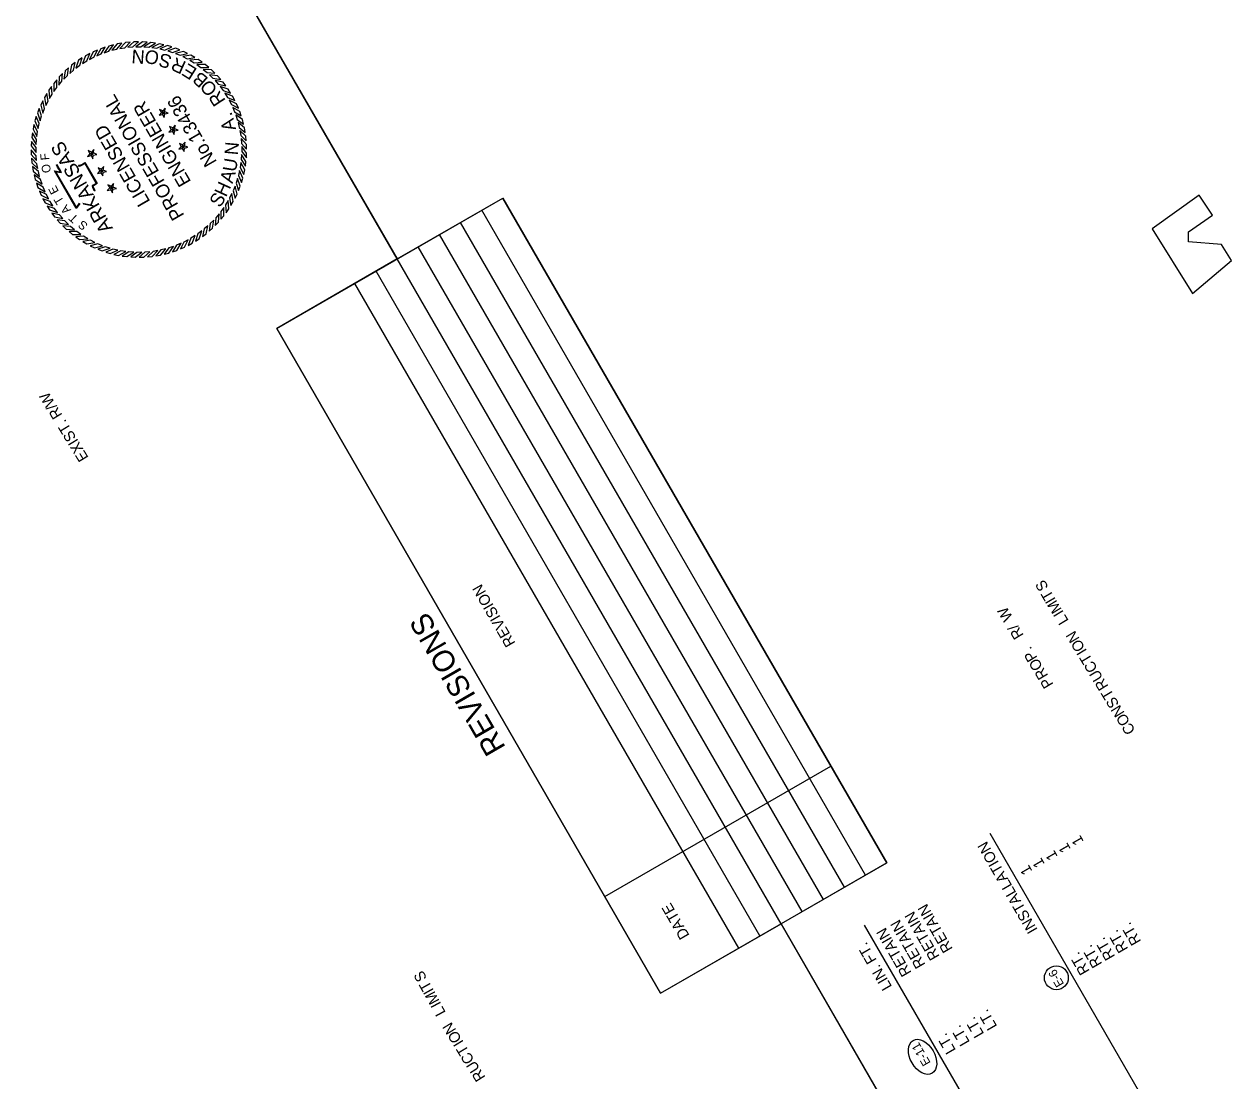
# Model space of a CAD drawing. Extents: x 956270 to 957915, y 1920230 to 1922423.
# Drawn here: x 956610 to 957279, y 1921447 to 1922032 of the extents above; entities that cross this region are included whole.
import ezdxf

# ---------------------------------------------------------------- set-up
doc = ezdxf.new("R2010")
doc.units = 0
for name, color, linetype in [('1', 7, 'Continuous'), ('44', 7, 'Continuous'), ('Default', 7, 'Continuous'), ('G-ANNO-SYMB', 7, 'Continuous'), ('NO PLOT', 7, 'Continuous'), ('R_Draft', 7, 'Continuous')]:
    doc.layers.add(name, color=color, linetype=linetype)

msp = doc.modelspace()

# ---------------------------------------------------------------- linework, layer by layer
at = {"layer": '1'}
for p, q in [((956816.66, 1921901.98), (956666.17, 1922162.65)), ((957172.25, 1921286.08), (957029.16, 1921533.92))]:
    msp.add_line(p, q, dxfattribs=at)
msp.add_circle((957181.5, 1921504.03), 6.61, dxfattribs=at)
msp.add_ellipse((957107.43, 1921460.25), major_axis=(-5.26, 9.11), ratio=0.638788, dxfattribs=at)
at = {"layer": '44'}
for p, q in [((957265.37, 1921375.21), (957144.87, 1921583.93)), ((957191.79, 1921331.56), (957075.39, 1921533.17))]:
    msp.add_line(p, q, dxfattribs=at)
at = {"layer": 'Default'}
for p, q in [((956749.98, 1921863.48), (956875.12, 1921935.73)), ((957087.62, 1921567.67), (956875.12, 1921935.73)), ((957075.93, 1921560.92), (956863.43, 1921928.98)), ((957064.24, 1921554.17), (956851.74, 1921922.23)), ((957052.55, 1921547.42), (956840.05, 1921915.48)), ((957040.85, 1921540.67), (956828.35, 1921908.73)), ((957040.85, 1921540.67), (956828.35, 1921908.73)), ((957029.16, 1921533.92), (956816.66, 1921901.98)), ((957017.47, 1921527.17), (956804.97, 1921895.23)), ((957005.78, 1921520.42), (956793.28, 1921888.48)), ((956962.48, 1921495.42), (956749.98, 1921863.48)), ((956931.57, 1921548.95), (957056.71, 1921621.2)), ((956962.48, 1921495.42), (957087.62, 1921567.67))]:
    msp.add_line(p, q, dxfattribs=at)
at = {"layer": 'G-ANNO-SYMB'}
for points in [[(956668.87, 1922022.03), (956666.32, 1922021.77), (956663.11, 1922018.51), (956665.85, 1922018.95)], [(956673.55, 1922022.22), (956670.99, 1922022.16), (956667.53, 1922019.16), (956670.3, 1922019.4)], [(956678.23, 1922022.05), (956675.67, 1922022.19), (956671.99, 1922019.47), (956674.77, 1922019.49)], [(956682.89, 1922021.51), (956680.34, 1922021.85), (956676.46, 1922019.43), (956679.23, 1922019.23)], [(956646.48, 1922015.66), (956644.22, 1922014.44), (956642.51, 1922010.2), (956644.87, 1922011.66)], [(956650.73, 1922017.63), (956648.38, 1922016.59), (956646.34, 1922012.5), (956648.81, 1922013.77)], [(956655.12, 1922019.26), (956652.7, 1922018.41), (956650.35, 1922014.49), (956652.9, 1922015.56)], [(956659.63, 1922020.54), (956657.15, 1922019.88), (956654.49, 1922016.16), (956657.12, 1922017.03)], [(956664.22, 1922021.47), (956661.7, 1922021.01), (956658.76, 1922017.5), (956661.45, 1922018.16)], [(956687.48, 1922020.61), (956684.97, 1922021.15), (956680.92, 1922019.04), (956683.66, 1922018.62)], [(956691.99, 1922019.35), (956689.54, 1922020.08), (956685.33, 1922018.3), (956688.02, 1922017.66)], [(956696.39, 1922017.74), (956694, 1922018.66), (956689.66, 1922017.21), (956692.3, 1922016.37)], [(956700.65, 1922015.79), (956698.34, 1922016.9), (956693.9, 1922015.79), (956696.47, 1922014.74)], [(956638.51, 1922010.75), (956636.47, 1922009.19), (956635.44, 1922004.73), (956637.54, 1922006.55)], [(956642.4, 1922013.36), (956640.24, 1922011.97), (956638.87, 1922007.6), (956641.1, 1922009.25)], [(956704.74, 1922013.51), (956702.52, 1922014.8), (956698.01, 1922014.04), (956700.49, 1922012.8)], [(956708.64, 1922010.91), (956706.53, 1922012.37), (956701.98, 1922011.97), (956704.35, 1922010.54)], [(956712.33, 1922008.02), (956710.34, 1922009.64), (956705.77, 1922009.6), (956708.02, 1922007.99)], [(956631.41, 1922004.65), (956629.64, 1922002.79), (956629.32, 1921998.23), (956631.11, 1922000.35)], [(956634.84, 1922007.84), (956632.93, 1922006.12), (956632.25, 1922001.6), (956634.2, 1922003.57)], [(956715.78, 1922004.85), (956713.92, 1922006.62), (956709.36, 1922006.94), (956711.48, 1922005.15)], [(956718.97, 1922001.42), (956717.25, 1922003.33), (956712.73, 1922004.01), (956714.7, 1922002.06)], [(956625.34, 1921997.52), (956623.89, 1921995.4), (956624.28, 1921990.85), (956625.72, 1921993.22)], [(956628.24, 1922001.2), (956626.62, 1921999.21), (956626.66, 1921994.64), (956628.27, 1921996.89)], [(956721.88, 1921997.75), (956720.32, 1921999.79), (956715.86, 1922000.82), (956717.67, 1921998.72)], [(956724.49, 1921993.86), (956723.09, 1921996.01), (956718.73, 1921997.39), (956720.37, 1921995.16)], [(956620.47, 1921989.52), (956619.36, 1921987.21), (956620.47, 1921982.77), (956621.52, 1921985.34)], [(956622.75, 1921993.61), (956621.46, 1921991.4), (956622.22, 1921986.89), (956623.46, 1921989.36)], [(956726.79, 1921989.78), (956725.57, 1921992.03), (956721.33, 1921993.75), (956722.79, 1921991.39)], [(956728.76, 1921985.53), (956727.72, 1921987.87), (956723.63, 1921989.91), (956724.9, 1921987.45)], [(956618.52, 1921985.26), (956617.6, 1921982.87), (956619.05, 1921978.53), (956619.89, 1921981.17)], [(956687.23, 1921982.98), (956686.19, 1921983.08), (956684.87, 1921981.61), (956686.8, 1921982.02)], [(956687.23, 1921982.98), (956687.01, 1921983.99), (956685.2, 1921984.8), (956686.19, 1921983.08)], [(956687.23, 1921982.98), (956686.8, 1921982.02), (956687.79, 1921980.31), (956688, 1921982.28)], [(956687.23, 1921982.98), (956688.13, 1921983.5), (956688.34, 1921985.47), (956687.01, 1921983.99)], [(956687.23, 1921982.98), (956688, 1921982.28), (956689.94, 1921982.69), (956688.13, 1921983.5)], [(956730.39, 1921981.14), (956729.54, 1921983.56), (956725.62, 1921985.91), (956726.69, 1921983.36)], [(956731.67, 1921976.63), (956731.01, 1921979.11), (956727.29, 1921981.77), (956728.16, 1921979.14)], [(956615.65, 1921976.35), (956615.11, 1921973.84), (956617.22, 1921969.79), (956617.64, 1921972.53)], [(956616.91, 1921980.86), (956616.18, 1921978.41), (956617.96, 1921974.2), (956618.59, 1921976.9)], [(956692.68, 1921973.53), (956692.47, 1921974.55), (956690.66, 1921975.35), (956691.65, 1921973.64)], [(956692.68, 1921973.53), (956693.58, 1921974.05), (956693.79, 1921976.02), (956692.47, 1921974.55)], [(956732.6, 1921972.04), (956732.13, 1921974.56), (956728.63, 1921977.5), (956729.29, 1921974.81)], [(956614.75, 1921971.76), (956614.41, 1921969.21), (956616.83, 1921965.34), (956617.03, 1921968.1)], [(956692.68, 1921973.53), (956691.65, 1921973.64), (956690.32, 1921972.16), (956692.26, 1921972.58)], [(956692.68, 1921973.53), (956692.26, 1921972.58), (956693.25, 1921970.86), (956693.46, 1921972.83)], [(956692.68, 1921973.53), (956693.46, 1921972.83), (956695.39, 1921973.24), (956693.58, 1921974.05)], [(956733.16, 1921967.39), (956732.9, 1921969.94), (956729.63, 1921973.15), (956730.08, 1921970.41)], [(956733.35, 1921962.71), (956733.29, 1921965.27), (956730.29, 1921968.72), (956730.52, 1921965.96)], [(956614.03, 1921962.42), (956614.1, 1921959.86), (956617.1, 1921956.41), (956616.86, 1921959.17)], [(956614.21, 1921967.1), (956614.07, 1921964.54), (956616.79, 1921960.87), (956616.77, 1921963.64)], [(956647.67, 1921960.13), (956647.45, 1921961.15), (956645.64, 1921961.96), (956646.63, 1921960.24)], [(956647.67, 1921960.13), (956648.57, 1921960.66), (956648.77, 1921962.63), (956647.45, 1921961.15)], [(956698.14, 1921964.08), (956697.1, 1921964.19), (956695.77, 1921962.72), (956697.71, 1921963.13)], [(956698.14, 1921964.08), (956697.92, 1921965.1), (956696.11, 1921965.91), (956697.1, 1921964.19)], [(956698.14, 1921964.08), (956697.71, 1921963.13), (956698.7, 1921961.41), (956698.91, 1921963.38)], [(956698.14, 1921964.08), (956699.04, 1921964.6), (956699.25, 1921966.57), (956697.92, 1921965.1)], [(956698.14, 1921964.08), (956698.91, 1921963.38), (956700.85, 1921963.8), (956699.04, 1921964.6)], [(956733.18, 1921958.03), (956733.32, 1921960.59), (956730.6, 1921964.26), (956730.62, 1921961.49)], [(956614.23, 1921957.74), (956614.49, 1921955.19), (956617.75, 1921951.98), (956617.31, 1921954.72)], [(956647.67, 1921960.13), (956646.63, 1921960.24), (956645.3, 1921958.77), (956647.24, 1921959.18)], [(956647.67, 1921960.13), (956647.24, 1921959.18), (956648.23, 1921957.47), (956648.44, 1921959.44)], [(956647.67, 1921960.13), (956648.44, 1921959.44), (956650.38, 1921959.85), (956648.57, 1921960.66)], [(956731.74, 1921948.78), (956732.28, 1921951.29), (956730.17, 1921955.34), (956729.75, 1921952.6)], [(956732.64, 1921953.37), (956732.98, 1921955.92), (956730.56, 1921959.79), (956730.36, 1921957.03)], [(956614.79, 1921953.09), (956615.25, 1921950.57), (956618.76, 1921947.63), (956618.09, 1921950.32)], [(956615.72, 1921948.5), (956616.37, 1921946.02), (956620.1, 1921943.36), (956619.23, 1921945.99)], [(956653.12, 1921950.69), (956652.08, 1921950.8), (956650.76, 1921949.32), (956652.7, 1921949.74)], [(956653.12, 1921950.69), (956652.9, 1921951.71), (956651.09, 1921952.51), (956652.08, 1921950.8)], [(956653.12, 1921950.69), (956652.7, 1921949.74), (956653.69, 1921948.02), (956653.89, 1921949.99)], [(956653.12, 1921950.69), (956654.02, 1921951.21), (956654.23, 1921953.18), (956652.9, 1921951.71)], [(956653.12, 1921950.69), (956653.89, 1921949.99), (956655.83, 1921950.4), (956654.02, 1921951.21)], [(956730.48, 1921944.27), (956731.21, 1921946.72), (956729.43, 1921950.93), (956728.79, 1921948.23)], [(956617, 1921943.99), (956617.85, 1921941.57), (956621.77, 1921939.22), (956620.69, 1921941.77)], [(956658.57, 1921941.24), (956658.36, 1921942.26), (956656.55, 1921943.06), (956657.54, 1921941.35)], [(956658.57, 1921941.24), (956659.48, 1921941.76), (956659.68, 1921943.73), (956658.36, 1921942.26)], [(956658.57, 1921941.24), (956659.35, 1921940.54), (956661.29, 1921940.95), (956659.48, 1921941.76)], [(956726.92, 1921935.61), (956728.03, 1921937.92), (956726.92, 1921942.36), (956725.87, 1921939.79)], [(956728.87, 1921939.87), (956729.79, 1921942.26), (956728.34, 1921946.6), (956727.5, 1921943.96)], [(956618.63, 1921939.6), (956619.67, 1921937.26), (956623.76, 1921935.22), (956622.49, 1921937.68)], [(956620.6, 1921935.35), (956621.82, 1921933.1), (956626.06, 1921931.38), (956624.6, 1921933.74)], [(956658.57, 1921941.24), (956657.54, 1921941.35), (956656.21, 1921939.88), (956658.15, 1921940.29)], [(956658.57, 1921941.24), (956658.15, 1921940.29), (956659.14, 1921938.57), (956659.35, 1921940.54)], [(956724.64, 1921931.52), (956725.92, 1921933.73), (956725.17, 1921938.24), (956723.93, 1921935.77)], [(956622.9, 1921931.27), (956624.29, 1921929.12), (956628.65, 1921927.74), (956627.01, 1921929.97)], [(956719.15, 1921923.93), (956720.77, 1921925.92), (956720.73, 1921930.49), (956719.11, 1921928.24)], [(956722.04, 1921927.61), (956723.5, 1921929.73), (956723.1, 1921934.28), (956721.67, 1921931.91)], [(956625.51, 1921927.38), (956627.07, 1921925.34), (956631.53, 1921924.31), (956629.71, 1921926.41)], [(956628.42, 1921923.71), (956630.13, 1921921.8), (956634.66, 1921921.12), (956632.69, 1921923.07)], [(956712.55, 1921917.29), (956714.46, 1921919.01), (956715.13, 1921923.53), (956713.19, 1921921.56)], [(956715.98, 1921920.48), (956717.75, 1921922.34), (956718.07, 1921926.9), (956716.28, 1921924.78)], [(956631.61, 1921920.28), (956633.47, 1921918.51), (956638.03, 1921918.19), (956635.91, 1921919.98)], [(956635.06, 1921917.11), (956637.05, 1921915.49), (956641.62, 1921915.53), (956639.37, 1921917.14)], [(956700.91, 1921909.47), (956703.16, 1921910.69), (956704.88, 1921914.93), (956702.52, 1921913.47)], [(956704.99, 1921911.77), (956707.14, 1921913.16), (956708.52, 1921917.53), (956706.28, 1921915.88)], [(956708.88, 1921914.38), (956710.92, 1921915.94), (956711.94, 1921920.4), (956709.85, 1921918.58)], [(956638.74, 1921914.22), (956640.85, 1921912.76), (956645.41, 1921913.16), (956643.04, 1921914.59)], [(956642.64, 1921911.62), (956644.86, 1921910.33), (956649.37, 1921911.09), (956646.9, 1921912.33)], [(956646.74, 1921909.34), (956649.05, 1921908.23), (956653.49, 1921909.34), (956650.92, 1921910.39)], [(956651, 1921907.39), (956653.39, 1921906.47), (956657.73, 1921907.92), (956655.08, 1921908.76)], [(956687.76, 1921904.59), (956690.24, 1921905.25), (956692.9, 1921908.97), (956690.26, 1921908.1)], [(956692.27, 1921905.87), (956694.69, 1921906.72), (956697.04, 1921910.64), (956694.49, 1921909.57)], [(956696.66, 1921907.5), (956699, 1921908.54), (956701.04, 1921912.63), (956698.58, 1921911.36)], [(956655.39, 1921905.78), (956657.85, 1921905.05), (956662.06, 1921906.83), (956659.36, 1921907.47)], [(956659.91, 1921904.52), (956662.41, 1921903.98), (956666.47, 1921906.09), (956663.73, 1921906.51)], [(956664.5, 1921903.62), (956667.05, 1921903.28), (956670.92, 1921905.7), (956668.16, 1921905.9)], [(956669.16, 1921903.08), (956671.72, 1921902.94), (956675.39, 1921905.66), (956672.62, 1921905.64)], [(956673.84, 1921902.91), (956676.4, 1921902.97), (956679.85, 1921905.97), (956677.09, 1921905.73)], [(956678.52, 1921903.1), (956681.07, 1921903.36), (956684.27, 1921906.62), (956681.54, 1921906.18)], [(956683.17, 1921903.66), (956685.69, 1921904.12), (956688.63, 1921907.63), (956685.94, 1921906.97)]]:
    msp.add_lwpolyline(points, close=True, dxfattribs=at)
for points in [[(956640.27, 1921954.03), (956640.76, 1921953.84), (956641.26, 1921953.97), (956642.41, 1921954.48), (956643.85, 1921955.31), (956650.57, 1921943.68), (956648.62, 1921942.56), (956648.19, 1921942.31), (956648.32, 1921941.75), (956649.27, 1921940.1), (956649, 1921939.54)], [(956640.97, 1921932.64), (956639.06, 1921929.93), (956627.02, 1921950.76), (956630.21, 1921950.28), (956629.37, 1921951.69), (956628.68, 1921952.86), (956628.12, 1921954.12)], [(956640.66, 1921932.86), (956639.09, 1921930.63), (956627.74, 1921950.27), (956630.95, 1921949.79), (956629.7, 1921951.88), (956629.02, 1921953.04), (956628.47, 1921954.27)], [(956640.13, 1921953.67), (956640.74, 1921953.44), (956641.39, 1921953.61), (956642.58, 1921954.14), (956643.71, 1921954.79), (956650.05, 1921943.82), (956648.43, 1921942.89), (956647.76, 1921942.5), (956647.96, 1921941.61), (956648.84, 1921940.08), (956648.65, 1921939.72)]]:
    msp.add_lwpolyline(points, dxfattribs=at)
at = {"layer": 'NO PLOT'}
for points in [[(957915.18, 1921041.6), (957117.5, 1922423.23), (956666.17, 1922162.65), (956816.66, 1921901.98), (956875.12, 1921935.73), (957087.62, 1921567.67), (957029.16, 1921533.92), (957172.25, 1921286.08), (957225.74, 1921316.96), (957397.07, 1921020.21), (957343.58, 1920989.33), (957463.85, 1920781.02)], [(957915.18, 1921041.6), (957117.5, 1922423.23), (956666.17, 1922162.65), (956816.66, 1921901.98), (956875.12, 1921935.73), (957087.62, 1921567.67), (957029.16, 1921533.92), (957172.25, 1921286.08), (957225.74, 1921316.96), (957397.07, 1921020.21), (957343.58, 1920989.33), (957463.85, 1920781.02)], [(957915.18, 1921041.6), (957117.5, 1922423.23), (956666.17, 1922162.65), (956816.66, 1921901.98), (956875.12, 1921935.73), (957087.62, 1921567.67), (957029.16, 1921533.92), (957172.25, 1921286.08), (957225.74, 1921316.96), (957397.07, 1921020.21), (957343.58, 1920989.33), (957463.85, 1920781.02)], [(957915.18, 1921041.6), (957117.5, 1922423.23), (956666.17, 1922162.65), (956816.66, 1921901.98), (956875.12, 1921935.73), (957087.62, 1921567.67), (957029.16, 1921533.92), (957172.25, 1921286.08), (957225.74, 1921316.96), (957397.07, 1921020.21), (957343.58, 1920989.33), (957463.85, 1920781.02)], [(957915.18, 1921041.6), (957117.5, 1922423.23), (956666.17, 1922162.65), (956816.66, 1921901.98), (956875.12, 1921935.73), (957087.62, 1921567.67), (957029.16, 1921533.92), (957172.25, 1921286.08), (957225.74, 1921316.96), (957397.07, 1921020.21), (957343.58, 1920989.33), (957463.85, 1920781.02)], [(957012.51, 1920520.44), (956420.48, 1921545.87), (956463.26, 1921570.57), (956365.36, 1921740.14), (956378, 1921747.44), (956270.25, 1921934.07), (956666.17, 1922162.65), (956816.66, 1921901.98), (956749.98, 1921863.48), (956962.48, 1921495.42), (957029.16, 1921533.92), (957172.25, 1921286.08), (957120.9, 1921256.43), (957292.23, 1920959.68), (957343.58, 1920989.33), (957463.85, 1920781.02)], [(957012.51, 1920520.44), (956420.48, 1921545.87), (956463.26, 1921570.57), (956365.36, 1921740.14), (956378, 1921747.44), (956270.25, 1921934.07), (956666.17, 1922162.65), (956816.66, 1921901.98), (956749.98, 1921863.48), (956962.48, 1921495.42), (957029.16, 1921533.92), (957172.25, 1921286.08), (957120.9, 1921256.43), (957292.23, 1920959.68), (957343.58, 1920989.33), (957463.85, 1920781.02)], [(957012.51, 1920520.44), (956420.48, 1921545.87), (956463.26, 1921570.57), (956365.36, 1921740.14), (956378, 1921747.44), (956270.25, 1921934.07), (956666.17, 1922162.65), (956816.66, 1921901.98), (956749.98, 1921863.48), (956962.48, 1921495.42), (957029.16, 1921533.92), (957172.25, 1921286.08), (957120.9, 1921256.43), (957292.23, 1920959.68), (957343.58, 1920989.33), (957463.85, 1920781.02)], [(957012.51, 1920520.44), (956420.48, 1921545.87), (956463.26, 1921570.57), (956365.36, 1921740.14), (956378, 1921747.44), (956270.25, 1921934.07), (956666.17, 1922162.65), (956816.66, 1921901.98), (956749.98, 1921863.48), (956962.48, 1921495.42), (957029.16, 1921533.92), (957172.25, 1921286.08), (957120.9, 1921256.43), (957292.23, 1920959.68), (957343.58, 1920989.33), (957463.85, 1920781.02)], [(957012.51, 1920520.44), (956420.48, 1921545.87), (956463.26, 1921570.57), (956365.36, 1921740.14), (956378, 1921747.44), (956270.25, 1921934.07), (956666.17, 1922162.65), (956816.66, 1921901.98), (956749.98, 1921863.48), (956962.48, 1921495.42), (957029.16, 1921533.92), (957172.25, 1921286.08), (957120.9, 1921256.43), (957292.23, 1920959.68), (957343.58, 1920989.33), (957463.85, 1920781.02)], [(957278.4, 1921901.15), (957272.97, 1921909.99), (957254.69, 1921911.42), (957254.66, 1921917), (957267.98, 1921926.32), (957260.45, 1921937.33), (957234.55, 1921918.67), (957256.76, 1921882.79)]]:
    msp.add_lwpolyline(points, close=True, dxfattribs=at)

# ---------------------------------------------------------------- texts
at = {"layer": '1'}
for s, rotation, p in [('E-6 ', 120, (957185.9, 1921500.57)), ('E-11', 119.99998, (957112.07, 1921456.93))]:
    msp.add_text(s, height=4.8, rotation=rotation, dxfattribs=at).set_placement(p)
at = {"layer": '44'}
for s, rotation, p in [('1', 120, (957196.83, 1921579.51)), ('INSTALLATION', 120, (957171.3, 1921530.64)), ('1', 120, (957182.43, 1921571.19)), ('1', 120, (957189.65, 1921575.36)), ('1', 120, (957175.25, 1921567.05)), ('1', 120, (957168.38, 1921563.08)), ('RETAIN', 119.99998, (957117.11, 1921515.87)), ('RETAIN', 119.99998, (957124.34, 1921520.04)), ('RETAIN', 119.99998, (957109.22, 1921511.31)), ('RT.', 120, (957228.6, 1921524.14)), ('RETAIN', 119.99998, (957101.48, 1921506.84)), ('RT.', 120, (957221.42, 1921519.99)), ('LIN. FT.', 119.99998, (957090.71, 1921499.12)), ('RT.', 120, (957207.03, 1921511.68)), ('RT.', 120, (957214.21, 1921515.83)), ('RT.', 120, (957200.15, 1921507.71)), ('LT.', 119.99998, (957141.69, 1921472.96)), ('LT.', 119.99998, (957148.92, 1921477.13)), ('LT.', 119.99998, (957133.81, 1921468.41)), ('LT.', 119.99998, (957126.06, 1921463.93))]:
    msp.add_text(s, height=6, rotation=rotation, dxfattribs=at).set_placement(p)
at = {"layer": 'Default'}
for s, height, p in [('REVISION', 6, (956882.3, 1921689.29)), ('REVISIONS', 12, (956876.99, 1921631.48)), ('DATE', 6, (956978.64, 1921527.43))]:
    msp.add_text(s, height=height, rotation=120, dxfattribs=at).set_placement(p)
at = {"layer": 'G-ANNO-SYMB'}
for s, height, rotation, p in [('N', 7.5, 176.10067, (956677.18, 1922017.39)), ('O', 7.5, 164.77573, (956685.63, 1922016.26)), ('S', 7.5, 163.48784, (956692.52, 1922014.28)), ('R', 7.5, 155.65967, (956700.38, 1922010.86)), ('E', 7.5, 147.83149, (956706.43, 1922007.03)), ('B', 7.5, 138.88501, (956712.56, 1922001.83)), ('O', 7.5, 131.42961, (956717.7, 1921996.11)), ('R', 7.5, 123.22866, (956721.95, 1921989.71)), ('PROFESSIONAL', 7.5, 120, (956699.08, 1921926.09)), ('ENGINEER', 7.5, 120, (956702.8, 1921944.73)), ('No.13436', 7.47, 120, (956717.1, 1921955.72)), ('.', 7.5, 111.30002, (956725.73, 1921981.27)), ('LICENSED', 7.5, 120, (956680.19, 1921933.73)), ('A', 7.5, 103.09908, (956727.52, 1921973.79)), ('ARKANSAS', 7.747, 120, (956659.49, 1921919.01)), ('N', 7.5, 84.93262, (956728.49, 1921959.25)), ('F', 4.75, 95.36282, (956624.14, 1921956.86)), ('U', 7.5, 80.90262, (956727.43, 1921949.91)), ('O', 4.75, 101.2218, (956625.18, 1921950.07)), ('A', 7.5, 73.44722, (956725.53, 1921943.42)), ('E', 4.75, 116.67203, (956629.53, 1921939.28)), ('H', 7.5, 65.61905, (956721.99, 1921935.87)), ('T', 4.75, 121.47887, (956632.44, 1921933.94)), ('S', 7.5, 58.16364, (956718.6, 1921929.97)), ('A', 4.75, 128.67877, (956636.32, 1921929.11)), ('T', 4.75, 136.90148, (956640.51, 1921924.87)), ('S', 4.75, 139.77256, (956645.87, 1921920.99))]:
    msp.add_text(s, height=height, rotation=rotation, dxfattribs=at).set_placement(p)
at = {"layer": 'R_Draft'}
for s, rotation, p in [('EXIST. R/W', 121.48809, (956646, 1921792.03)), ('S', 120.26716, (957177.35, 1921720.24)), ('T', 120.26716, (957180.3, 1921715.18)), ('I', 120.26716, (957181.3, 1921713.47)), ('W', 121.18992, (957157.64, 1921703.55)), ('M', 121.40689, (957184.67, 1921708)), ('I', 121.40689, (957185.71, 1921706.31)), ('L', 121.31637, (957188.51, 1921701.71)), ('/', 121.18992, (957160.68, 1921698.54)), ('R', 121.18992, (957163.61, 1921693.69)), ('N', 121.01897, (957194.54, 1921691.72)), ('O', 121.01897, (957197.56, 1921686.7)), ('P', 121.18992, (957171.17, 1921681.2)), ('.', 121.18992, (957168.24, 1921686.05)), ('I', 121.36248, (957198.61, 1921685.01)), ('T', 121.36248, (957201.66, 1921680.01)), ('O', 121.18992, (957174.21, 1921676.19)), ('R', 121.18992, (957177.14, 1921671.34)), ('C', 120.9351, (957204.57, 1921675.14)), ('P', 121.18992, (957180.08, 1921666.49)), ('U', 120.78654, (957207.51, 1921670.19)), ('R', 121.73269, (957210.53, 1921665.39)), ('T', 120.85683, (957213.56, 1921660.38)), ('S', 120.85683, (957216.47, 1921655.51)), ('N', 121.93286, (957219.45, 1921650.69)), ('O', 121.93286, (957222.55, 1921645.72)), ('C', 121.15736, (957225.48, 1921640.86)), ('S', 118.29727, (956833.31, 1921503.74)), ('T', 119.29319, (956836.13, 1921498.72)), ('I', 119.29319, (956837.1, 1921496.99)), ('M', 118.21281, (956840.23, 1921491.25)), ('I', 118.21281, (956841.17, 1921489.5)), ('L', 118.21281, (956843.71, 1921484.75)), ('N', 121.66831, (956849.51, 1921475.05)), ('O', 121.66831, (956852.59, 1921470.06)), ('I', 121.66831, (956853.63, 1921468.37)), ('T', 121.01485, (956856.67, 1921463.29)), ('C', 121.01485, (956859.59, 1921458.43)), ('U', 122.5762, (956862.68, 1921453.75)), ('R', 122.52216, (956865.73, 1921448.96))]:
    msp.add_text(s, height=6, rotation=rotation, dxfattribs=at).set_placement(p)

doc.saveas('drawing.dxf')
